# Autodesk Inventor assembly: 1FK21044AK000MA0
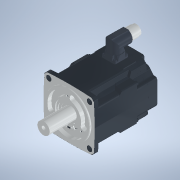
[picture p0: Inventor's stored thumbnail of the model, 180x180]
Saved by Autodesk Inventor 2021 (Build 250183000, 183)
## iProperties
Category: PARTsolutions
Created: 2026-06
Part Number: 1FK21044AK000MA0
Catalog Web Link: www.3dfindit.com
Description: 1FK21044AK000MA0-Servo synchronous motor
Document SubType Name: Assembly
Designer: psAdmin
Mass: 565.652 g
Surface Area: 988.094 cm^2
Volume: 565.652 cm^3
Density: 1 g/cm^3
Title: 1FK21044AK000MA0
Author: Cadenas PARTsolutions
Comments: Servo synchronous motor
PSOL_IDENT_0: {$CADENAS_DATA/23d-libs/siemens_ag/_cat_/87/f4/1fk21044ak000ma0.prj},193 {STYP=ASS},{VTYP=3D},{NB=1F
PSOL_IDENT_1: K21044AK000MA0},{LINA=1FK21044AK000MA0},{NN=1FK21044AK000MA0},{DATE=19.08.2025 14:00:48},{GEOMDATE=3
PSOL_IDENT_2: 0.07.2025 02:00:50},{VERSION=},{LINEID=10},{WBVAR=},{WBNUMERIC=}  {NB=1FK21044AK000MA0},{LINA=1FK210
PSOL_IDENT_3: 44AK000MA0},{KT=DUMMY},{PREVIEW=../../../_pool_/cb/72/p_d211_xx_00434j.png},{DESCSHORT=SIMOTICS S-1F
PSOL_IDENT_4: K2 HD, SINAMICS S210 3AC 400V-480V, 0.95 Nm, 6000 rpm},{DESCLONG=SIMOTICS S-1FK2 HD servo motor M0=1
PSOL_IDENT_5: .27 Nm; PN = 0.6 kW at nN=6000 rpm (380-480 V); PN = 0.4 kW at nN=3000 rpm (200-240 V); degree of pr
PSOL_IDENT_6: otection IP64; cylindrical shaft D19x40mm; absolute encoder 22-bit + 12-bit multiturn (encoder AM22D
PSOL_IDENT_7: QC); with OCC interface; plug size M17, rotatable; SIMOTICS S-1FK2 servomotorfor a wide range of use
PSOL_IDENT_8: s in industrial environments. SIMOTICS S‑1FK2 servomotors are compact synchronous motors with a high
PSOL_IDENT_9: dynamic performance that set themselves apart as a result of their high power density, degree of pr
PSOL_IDENT_10: otection and overload capability. The motors are available in two variants: as High Dynamic variant
PSOL_IDENT_11: (highest dynamic performance as a result of the low intrinsic moment of inertia for applications dem
PSOL_IDENT_12: anding a high dynamic performance with low moved masses) - and as Compact variant (precise and stabl
PSOL_IDENT_13: e closed-loop control for medium up to large moved masses as a result of a medium intrinsic moment o
PSOL_IDENT_14: f inertia). SIMOTICSS‑1FK2 servomotors fully exploit their strengths in a system with the SINAMICSS2
PSOL_IDENT_15: 10 frequency converter and simple connection using the one cable connection (OCC). Advantages includ
PSOL_IDENT_16: e the short control and positioning times, fast and precise correction of disturbing quantities as w
PSOL_IDENT_17: ell as stable control with a high dynamic performance. The servo motors can be configured to address
PSOL_IDENT_18: a wide range of requirements. For example with and without holding brake, IP64 or IP65 degree of pr
PSOL_IDENT_19: otection, singleturn or multiturn absolute encoders - to name just a few. Further, the servomotors a
PSOL_IDENT_20: re available in different shaft heights extending from 20 to 100. A shaft sealing ring is available
PSOL_IDENT_21: to achieve an IP65 degree of protection and for subsequent mounting at the motor or as spare part. S
PSOL_IDENT_22: IMOTICS - the optimum motor for each and every motion control application.},{INTNO=195125056312},{SU
PSOL_IDENT_23: PPLIERALTNO=1FK2104-4AK00-0MA0},{MANUID=1FK21044AK000MA0},{MANUNAME=Siemens},{MANUTYPEDESC=Synchrono
PSOL_IDENT_24: us motor 1FK2-HD 1,27 Nm},{AAU732=SIMOTICS},{AAO057=S-1FK2},{AAU734=SIMOTICS S-1FK2 HD servo motor M
PSOL_IDENT_25: 0=1.27 Nm; PN = 0.6 kW at nN=6000 rpm (380-480 V); PN = 0.4 kW at nN=3000 rpm (200-240 V); degree of
PSOL_IDENT_26: protection IP64; cylindrical shaft D19x40mm; absolute encoder 22-bit + 12-bit multiturn (encoder AM
PSOL_IDENT_27: 22DQC); with OCC interface; plug size M17, rotatable;},{AAW338=Synchronous motor 1FK2-HD 1,27 Nm},{A
PSOL_IDENT_28: AO742=SIMOTICS},{AAO663=4042948690994},{NOCUPEROU=1},{PRICEQUANTITY=1},{QUANTITYMIN=1},{QUANTITYINT=
PSOL_IDENT_29: 1},{CTN=85015100},{COO=DE},{AAO676=1FK2104-4AK00-0MA0},{AAO677=Siemens AG},{ORDERUNIT=C62},{CONTENTU
PSOL_IDENT_30: NIT=C62}
NB: 1FK21044AK000MA0
NN: 1FK21044AK000MA0
NT: Servo synchronous motor
NBSYN: $MANUID.
LINA: 1FK21044AK000MA0
CATALOG: SIEMENS
PREVIEW: ../../../_pool_/cb/72/p_d211_xx_00434j.png
DESCSHORT: SIMOTICS S-1FK2 HD, SINAMICS S210 3AC 400V-480V, 0.95 Nm, 6000 rpm
DESCLONG: SIMOTICS S-1FK2 HD servo motor M0=1.27 Nm; PN = 0.6 kW at nN=6000 rpm (380-480 V); PN = 0.4 kW at nN=3000 rpm (200-240 V); degree of protection IP64; cylindrica
INTNO: 195125056312
SUPPLIERALTNO: 1FK2104-4AK00-0MA0
MANUID: 1FK21044AK000MA0
MANUNAME: Siemens
MANUTYPEDESC: Synchronous motor 1FK2-HD 1,27 Nm
AAU732: SIMOTICS
AAO057: S-1FK2
AAU734: SIMOTICS S-1FK2 HD servo motor M0=1.27 Nm; PN = 0.6 kW at nN=6000 rpm (380-480 V); PN = 0.4 kW at nN=3000 rpm (200-240 V); degree of protection IP64; cylindrica
AAW338: Synchronous motor 1FK2-HD 1,27 Nm
AAO742: SIMOTICS
AAO663: 4042948690994.0
NOCUPEROU: 1
PRICEQUANTITY: 1
QUANTITYMIN: 1
QUANTITYINT: 1
CTN: 85015100
COO: DE
ARTICLENO: 1FK21044AK000MA0
BOMINFO: 1FK21044AK000MA0
CREATOR: CADENAS GmbH
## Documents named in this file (24)
- e:\temp\worker_COMMON_12\temp\tmp_2820_8_zeCPn\format_0\1FK21044AK000MA0.iam
- e:\temp\worker_COMMON_12\temp\tmp_2820_8_zeCPn\format_0\1FK21044AK000MA0_PART1.ipt
- e:\temp\worker_COMMON_12\temp\tmp_2820_8_zeCPn\format_0\1FK21044AK000MA0_PART2.ipt
- e:\temp\worker_COMMON_12\temp\tmp_2820_8_zeCPn\format_0\1FK21044AK000MA0_PART3.ipt
- e:\temp\worker_COMMON_12\temp\tmp_2820_8_zeCPn\format_0\1FK21044AK000MA0_PART4.ipt
- e:\temp\worker_COMMON_12\temp\tmp_2820_8_zeCPn\format_0\1FK21044AK000MA0_PART5.ipt
- e:\temp\worker_COMMON_12\temp\tmp_2820_8_zeCPn\format_0\1FK21044AK000MA0_PART6.ipt
- e:\temp\worker_COMMON_12\temp\tmp_2820_8_zeCPn\format_0\1FK21044AK000MA0_PART7.ipt
- e:\temp\worker_COMMON_12\temp\tmp_2820_8_zeCPn\format_0\1FK21044AK000MA0_PART8.ipt
- e:\temp\worker_COMMON_12\temp\tmp_2820_8_zeCPn\format_0\1FK21044AK000MA0_PART9.ipt
- e:\temp\worker_COMMON_12\temp\tmp_2820_8_zeCPn\format_0\1FK21044AK000MA0_PART10.ipt
- e:\temp\worker_COMMON_12\temp\tmp_2820_8_zeCPn\format_0\1FK21044AK000MA0_PART11.ipt
- e:\temp\worker_COMMON_12\temp\tmp_2820_8_zeCPn\format_0\1FK21044AK000MA0_PART12.ipt
- e:\temp\worker_COMMON_12\temp\tmp_2820_8_zeCPn\format_0\1FK21044AK000MA0_PART13.ipt
- e:\temp\worker_COMMON_12\temp\tmp_2820_8_zeCPn\format_0\1FK21044AK000MA0_PART14.ipt
- e:\temp\worker_COMMON_12\temp\tmp_2820_8_zeCPn\format_0\1FK21044AK000MA0_PART15.ipt
- e:\temp\worker_COMMON_12\temp\tmp_2820_8_zeCPn\format_0\1FK21044AK000MA0_PART16.ipt
- e:\temp\worker_COMMON_12\temp\tmp_2820_8_zeCPn\format_0\1FK21044AK000MA0_PART17.ipt
- e:\temp\worker_COMMON_12\temp\tmp_2820_8_zeCPn\format_0\1FK21044AK000MA0_PART18.ipt
- e:\temp\worker_COMMON_12\temp\tmp_2820_8_zeCPn\format_0\1FK21044AK000MA0_PART19.ipt
- e:\temp\worker_COMMON_12\temp\tmp_2820_8_zeCPn\format_0\1FK21044AK000MA0_PART20.ipt
- e:\temp\worker_COMMON_12\temp\tmp_2820_8_zeCPn\format_0\1FK21044AK000MA0_PART21.ipt
- e:\temp\worker_COMMON_12\temp\tmp_2820_8_zeCPn\format_0\1FK21044AK000MA0_PART22.ipt
- e:\temp\worker_COMMON_12\temp\tmp_2820_8_zeCPn\format_0\1FK21044AK000MA0_PART23.ipt
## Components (23 placed, 23 different names)
1. 1FK21044AK000MA0_PART1:1
2. 1FK21044AK000MA0_PART2:1
3. 1FK21044AK000MA0_PART3:1
4. 1FK21044AK000MA0_PART4:1
5. 1FK21044AK000MA0_PART5:1
6. 1FK21044AK000MA0_PART6:1
7. 1FK21044AK000MA0_PART7:1
8. 1FK21044AK000MA0_PART8:1
9. 1FK21044AK000MA0_PART9:1
10. 1FK21044AK000MA0_PART10:1
11. 1FK21044AK000MA0_PART11:1
12. 1FK21044AK000MA0_PART12:1
13. 1FK21044AK000MA0_PART13:1
14. 1FK21044AK000MA0_PART14:1
15. 1FK21044AK000MA0_PART15:1
16. 1FK21044AK000MA0_PART16:1
17. 1FK21044AK000MA0_PART17:1
18. 1FK21044AK000MA0_PART18:1
19. 1FK21044AK000MA0_PART19:1
20. 1FK21044AK000MA0_PART20:1
21. 1FK21044AK000MA0_PART21:1
22. 1FK21044AK000MA0_PART22:1
23. 1FK21044AK000MA0_PART23:1
